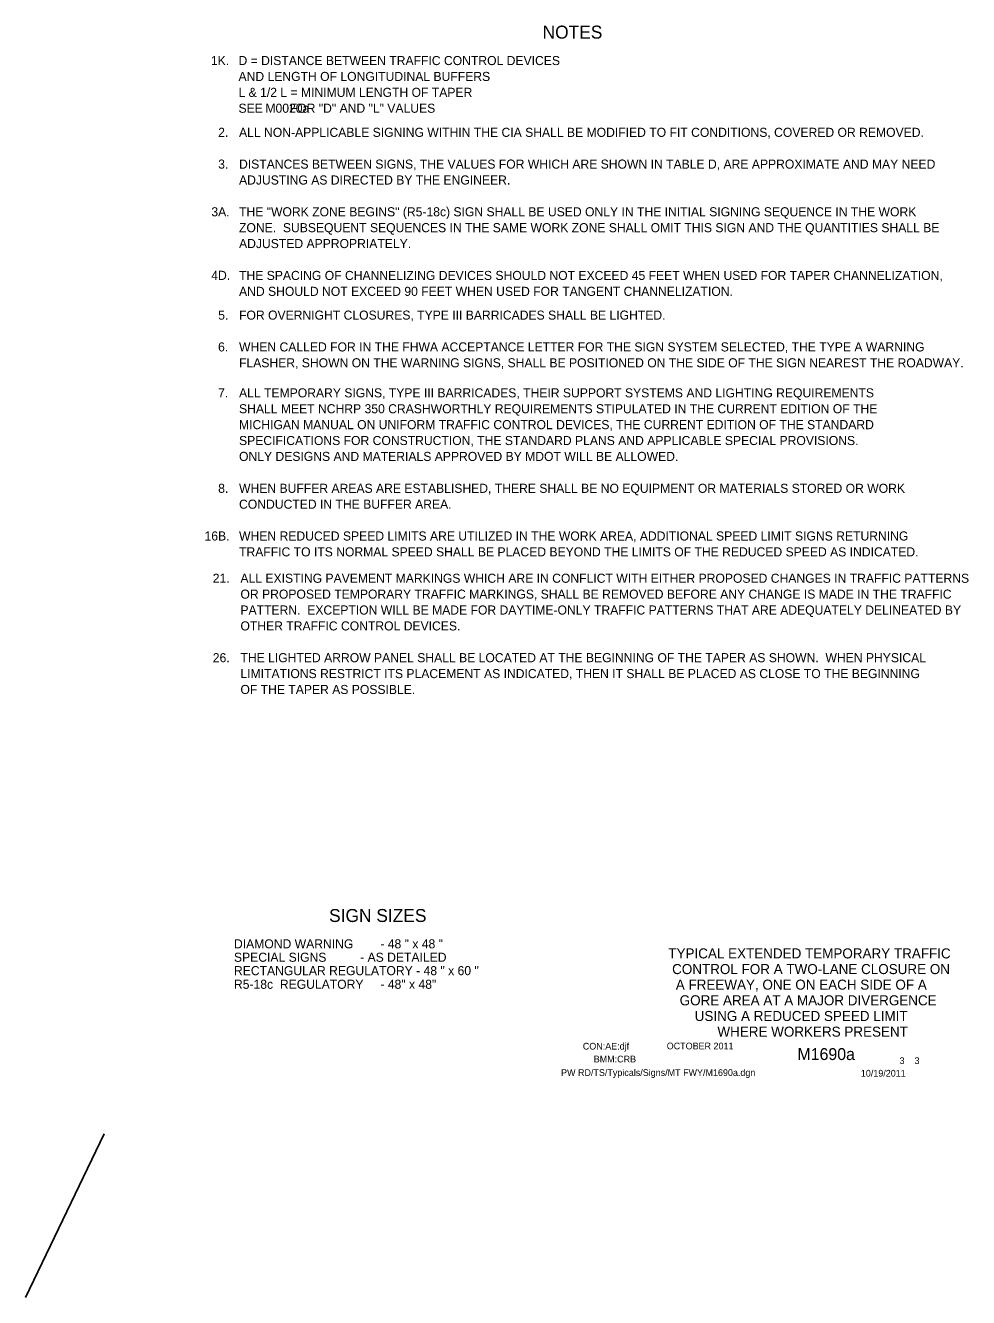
# Model space of a CAD drawing. Extents: x 16486 to 19506, y 5576 to 7023.
# Drawn here: x 18633 to 19506, y 5729 to 6905 of the extents above; entities that cross this region are included whole.
import ezdxf

# ---------------------------------------------------------------- set-up
doc = ezdxf.new("R2010")
doc.units = 0
for name, color, linetype in [('BORDER', 7, 'Continuous'), ('BORDER_SIGNAL_WO', 7, 'Continuous'), ('TYPICAL_TEXT_DIMEN_PR', 7, 'Continuous')]:
    doc.layers.add(name, color=color, linetype=linetype)

msp = doc.modelspace()

# ---------------------------------------------------------------- linework, layer by layer
at = {"layer": 'TYPICAL_TEXT_DIMEN_PR'}
msp.add_line((18705.8, 5880), (18633.1, 5728.7), dxfattribs=at)

# ---------------------------------------------------------------- texts
at = {"layer": 'BORDER'}
for s, p in [('TYPICAL EXTENDED TEMPORARY TRAFFIC', (19227.8, 6042.4)), ('CONTROL FOR A TWO-LANE CLOSURE ON', (19231.3, 6027.9)), ('A FREEWAY, ONE ON EACH SIDE OF A', (19234.7, 6013.5)), ('GORE AREA AT A MAJOR DIVERGENCE', (19238.3, 5999)), ('USING A REDUCED SPEED LIMIT', (19252.2, 5984.5)), ('WHERE WORKERS PRESENT', (19273.2, 5970))]:
    msp.add_text(s, height=9.3, dxfattribs=at).set_placement(p)
at = {"layer": 'BORDER_SIGNAL_WO'}
for s, height, p in [('CON:AE:djf  ', 6.2, (19148.7, 5958.1)), ('    OCTOBER 2011    ', 6.2, (19217.1, 5958.3)), ('    M1690a   ', 11, (19330.9, 5948.4)), ('BMM:CRB   ', 6.2, (19158.8, 5946.2)), (' 3    3 ', 6.2, (19439.4, 5944.7)), ('PW RD/TS/Typicals/Signs/MT FWY/M1690a.dgn      ', 6.2, (19128.6, 5933.7)), ('10/19/2011    ', 6.2, (19405.9, 5933.1))]:
    msp.add_text(s, height=height, dxfattribs=at).set_placement(p)
at = {"layer": 'TYPICAL_TEXT_DIMEN_PR'}
for s, height, p in [('NOTES', 12, (19111.5, 6893.3)), ('1K.', 8.4, (18804.7, 6868.8)), ('D = DISTANCE BETWEEN TRAFFIC CONTROL DEVICES', 8.4, (18830.2, 6868.8)), ('AND LENGTH OF LONGITUDINAL BUFFERS', 8.4, (18830.2, 6854.1)), ('L & 1/2 L = MINIMUM LENGTH OF TAPER', 8.4, (18830.2, 6839.4)), ('SEE        FOR "D" AND "L" VALUES', 8.4, (18830.2, 6824.7)), ('M0020a', 8.4, (18855.1, 6824.7)), ('2.', 8.4, (18811.4, 6802.4)), ('ALL NON-APPLICABLE SIGNING WITHIN THE CIA SHALL BE MODIFIED TO FIT CONDITIONS, COVERED OR REMOVED.', 8.4, (18830.7, 6802.4)), ('3.', 8.4, (18811.4, 6773)), ('DISTANCES BETWEEN SIGNS, THE VALUES FOR WHICH ARE SHOWN IN TABLE D, ARE APPROXIMATE AND MAY NEED', 8.4, (18830.7, 6773)), ('ADJUSTING AS DIRECTED BY THE ENGINEER.', 8.4, (18830.7, 6758.3)), ('3A.', 8.4, (18805.1, 6728.9)), ('THE "WORK ZONE BEGINS" (R5-18c) SIGN SHALL BE USED ONLY IN THE INITIAL SIGNING SEQUENCE IN THE WORK', 8.4, (18830.7, 6728.9)), ('ZONE.  SUBSEQUENT SEQUENCES IN THE SAME WORK ZONE SHALL OMIT THIS SIGN AND THE QUANTITIES SHALL BE', 8.4, (18830.7, 6714.2)), ('ADJUSTED APPROPRIATELY.', 8.4, (18830.7, 6699.5)), ('4D.', 8.4, (18805, 6670.1)), ('THE SPACING OF CHANNELIZING DEVICES SHOULD NOT EXCEED 45 FEET WHEN USED FOR TAPER CHANNELIZATION,', 8.4, (18830.7, 6670)), ('AND SHOULD NOT EXCEED 90 FEET WHEN USED FOR TANGENT CHANNELIZATION.', 8.4, (18830.7, 6655.3)), ('5.', 8.4, (18811.4, 6633.3)), ('FOR OVERNIGHT CLOSURES, TYPE III BARRICADES SHALL BE LIGHTED.', 8.4, (18830.7, 6633.3)), ('6.', 8.4, (18811.3, 6603.9)), ('WHEN CALLED FOR IN THE FHWA ACCEPTANCE LETTER FOR THE SIGN SYSTEM SELECTED, THE TYPE A WARNING ', 8.4, (18830.7, 6603.9)), ('FLASHER, SHOWN ON THE WARNING SIGNS, SHALL BE POSITIONED ON THE SIDE OF THE SIGN NEAREST THE ROADWAY.', 8.4, (18830.7, 6589.2)), ('7.', 8.4, (18811.3, 6561.3)), ('ALL TEMPORARY SIGNS, TYPE III BARRICADES, THEIR SUPPORT SYSTEMS AND LIGHTING REQUIREMENTS', 8.4, (18830.7, 6561.4)), ('SHALL MEET NCHRP 350 CRASHWORTHLY REQUIREMENTS STIPULATED IN THE CURRENT EDITION OF THE', 8.4, (18830.7, 6546.7)), ('MICHIGAN MANUAL ON UNIFORM TRAFFIC CONTROL DEVICES, THE CURRENT EDITION OF THE STANDARD', 8.4, (18830.7, 6532)), ('SPECIFICATIONS FOR CONSTRUCTION, THE STANDARD PLANS AND APPLICABLE SPECIAL PROVISIONS.', 8.4, (18830.7, 6517.3)), ('ONLY DESIGNS AND MATERIALS APPROVED BY MDOT WILL BE ALLOWED.', 8.4, (18830.7, 6502.6)), ('8.', 8.4, (18811.4, 6473.1)), ('WHEN BUFFER AREAS ARE ESTABLISHED, THERE SHALL BE NO EQUIPMENT OR MATERIALS STORED OR WORK     ', 8.4, (18830.7, 6473.1)), ('CONDUCTED IN THE BUFFER AREA.', 8.4, (18830.7, 6458.4)), ('16B.', 8.4, (18798.8, 6429)), ('WHEN REDUCED SPEED LIMITS ARE UTILIZED IN THE WORK AREA, ADDITIONAL SPEED LIMIT SIGNS RETURNING', 8.4, (18830.7, 6429)), ('TRAFFIC TO ITS NORMAL SPEED SHALL BE PLACED BEYOND THE LIMITS OF THE REDUCED SPEED AS INDICATED.', 8.4, (18830.7, 6414.3)), ('21.', 8.4, (18806.4, 6389.9)), ('ALL EXISTING PAVEMENT MARKINGS WHICH ARE IN CONFLICT WITH EITHER PROPOSED CHANGES IN TRAFFIC PATTERNS', 8.4, (18832, 6389.9)), ('OR PROPOSED TEMPORARY TRAFFIC MARKINGS, SHALL BE REMOVED BEFORE ANY CHANGE IS MADE IN THE TRAFFIC', 8.4, (18832, 6375.2)), ('PATTERN.  EXCEPTION WILL BE MADE FOR DAYTIME-ONLY TRAFFIC PATTERNS THAT ARE ADEQUATELY DELINEATED BY', 8.4, (18832, 6360.5)), ('OTHER TRAFFIC CONTROL DEVICES.', 8.4, (18832, 6345.8)), ('26.', 8.4, (18806.4, 6316.4)), ('THE LIGHTED ARROW PANEL SHALL BE LOCATED AT THE BEGINNING OF THE TAPER AS SHOWN.  WHEN PHYSICAL', 8.4, (18832, 6316.4)), ('LIMITATIONS RESTRICT ITS PLACEMENT AS INDICATED, THEN IT SHALL BE PLACED AS CLOSE TO THE BEGINNING', 8.4, (18832, 6301.7)), ('OF THE TAPER AS POSSIBLE.', 8.4, (18832, 6287)), ('SIGN SIZES', 12, (18914, 6076.1)), ('DIAMOND WARNING        - 48 " x 48 "', 8.4, (18826, 6051.7)), ('SPECIAL SIGNS          - AS DETAILED', 8.4, (18826, 6039.3)), ('RECTANGULAR REGULATORY - 48 " x 60 "', 8.4, (18826, 6026.9)), ('R5-18c  REGULATORY     - 48" x 48"', 8.4, (18826, 6014.3))]:
    msp.add_text(s, height=height, dxfattribs=at).set_placement(p)

doc.saveas('drawing.dxf')
